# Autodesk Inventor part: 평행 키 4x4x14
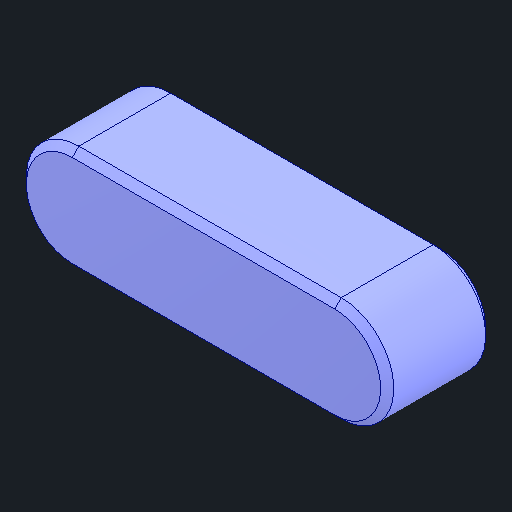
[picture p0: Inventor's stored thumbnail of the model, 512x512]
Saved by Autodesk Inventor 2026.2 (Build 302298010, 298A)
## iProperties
Created: 2026-03
Part Number: 평행 키 4x4x14
Material: 강철, 연강
Description: 키 및 해당 키홈
Document SubType Name: Modeling
Designer: PC2-02
Density: 7.85 g/cm^3
Appearance: 기본값
Author: jhkim
Sending System: Autodesk Inventor 2026
Preprocessor: ST-DEVELOPER v20.1
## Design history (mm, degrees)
feature "Solid1"
node "솔리드1"
